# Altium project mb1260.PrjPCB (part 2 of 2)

## Sheet STM32F7.SchDoc: STM32F723e Connexion
size A3; Author: N.P; CompanyName: STMicroelectronics; Organization: MCD/APPLIS/LMS; DocumentNumber: MB1260; Revision: D-01; SheetNumber: 3; SheetTotal: 12; Project: STM32F723e-DISCO; BOM Version: D-01
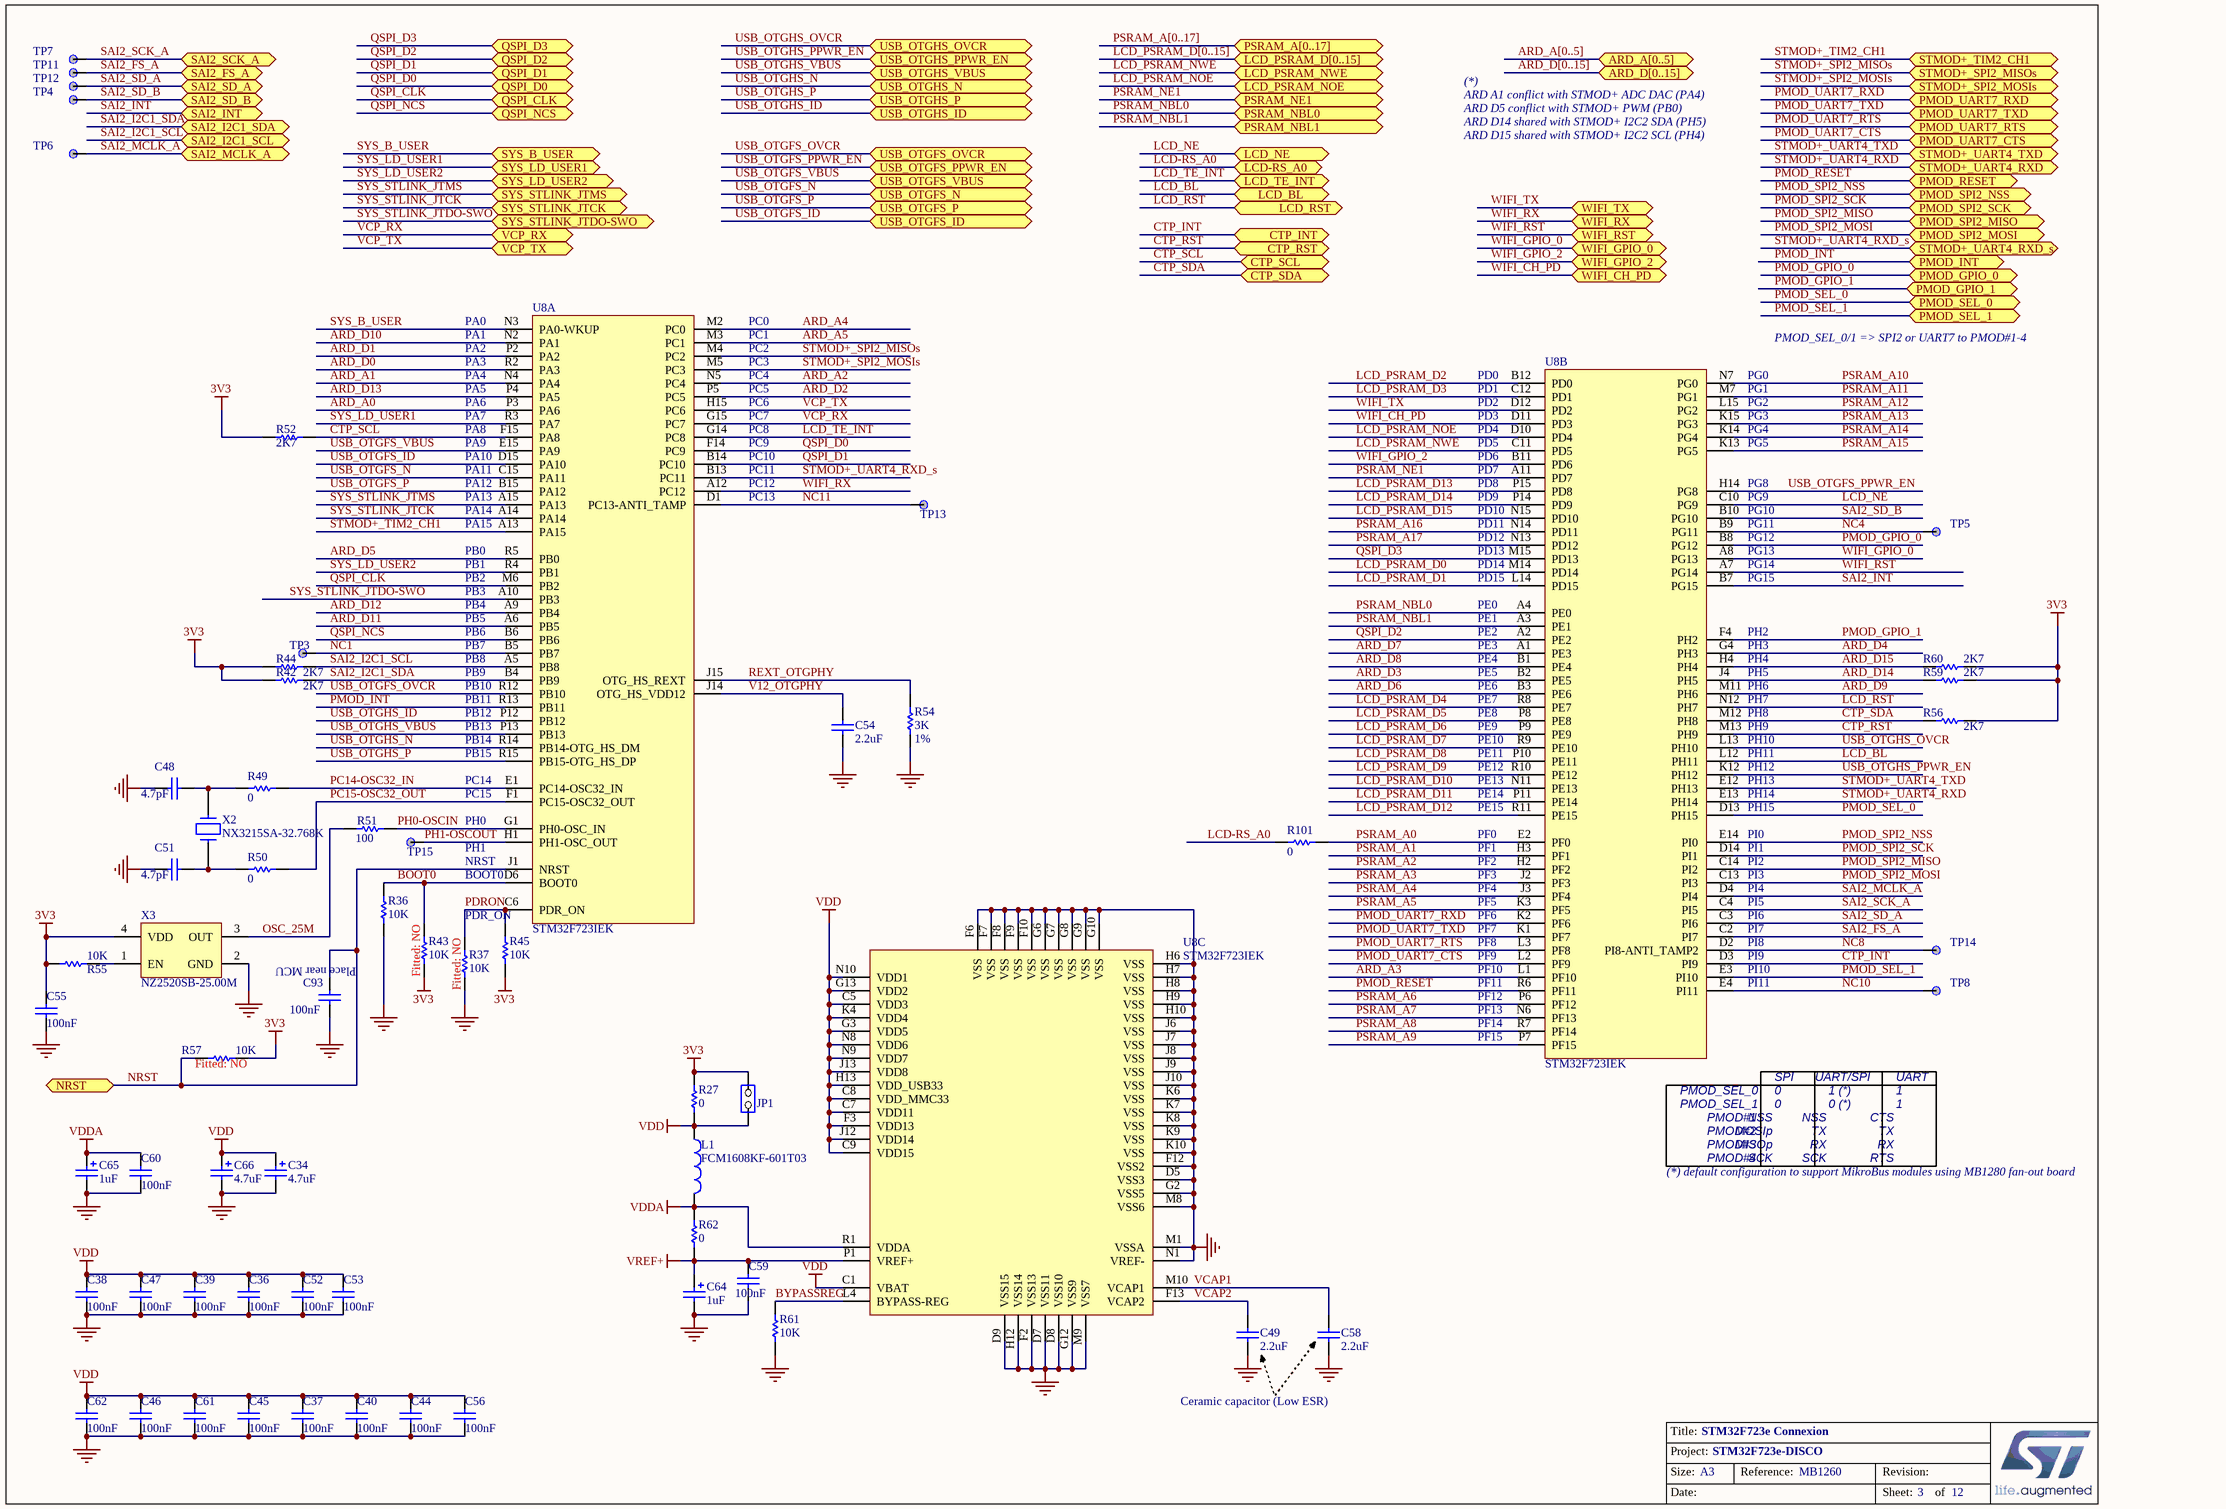
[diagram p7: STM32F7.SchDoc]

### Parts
C34  4.7uF  [TAN-A]
C36  100nF  [0402C]
C37  100nF  [0402C]
C38  100nF  [0402C]
C39  100nF  [0402C]
C40  100nF  [0402C]
C44  100nF  [0402C]
C45  100nF  [0402C]
C46  100nF  [0402C]
C47  100nF  [0402C]
C48  value 4.7pF  [0402C]  (hidden comment: 4.7pF_NPO_-+0.25pF_0402)
C49  2.2uF  [1206C]
C51  value 4.7pF  [0402C]  (hidden comment: 4.7pF_NPO_-+0.25pF_0402)
C52  100nF  [0402C]
C53  100nF  [0402C]
C54  value 2.2uF  [0603C]  (hidden comment: 2.2uF_X5R_10%_0603)
C55  100nF  [0402C]
C56  100nF  [0402C]
C58  2.2uF  [1206C]
C59  100nF  [0402C]
C60  100nF  [0402C]
C61  100nF  [0402C]
C62  100nF  [0402C]
C64  1uF  [TAN-A]
C65  1uF  [TAN-A]
C66  4.7uF  [TAN-A]
C93  100nF  [0402C]
JP1  JP2  [SIP2]  (value not drawn)
L1  FCM1608KF-601T03  [0603L]
R27  value 0  [0603R-GS]  (hidden comment: 0_5%_0603)
R36  10K  [0402R]
R37  Fitted: NO  [0402R]  (hidden comment: 10K)
R42  2K7  [0402R]
R43  Fitted: NO  [0402R]  (hidden comment: 10K)
R44  2K7  [0402R]
R45  10K  [0402R]
R49  0  [0402R]
R50  0  [0402R]
R51  100  [0402R]
R52  2K7  [0402R]
R54  3K  Tolerance: 1%  [0402R]
R55  10K  [0402R]
R56  2K7  [0402R]
R57  Fitted: NO  [0402R]  (hidden comment: 10K)
R59  2K7  [0402R]
R60  2K7  [0402R]
R61  10K  [0402R]
R62  value 0  [0603R-GS]  (hidden comment: 0_5%_0603)
R101  0  [0402R]
TP3  TP  [TP_C40]  (value not drawn)
TP4  TP  [TP_C40]  (value not drawn)
TP5  TP  [TP_C40]  (value not drawn)
TP6  TP  [TP_C40]  (value not drawn)
TP7  TP  [TP_C40]  (value not drawn)
TP8  TP  [TP_C40]  (value not drawn)
TP11  TP  [TP_C40]  (value not drawn)
TP12  TP  [TP_C40]  (value not drawn)
TP13  TP  [TP_C40]  (value not drawn)
TP14  TP  [TP_C40]  (value not drawn)
TP15  TP  [TP_C40]  (value not drawn)
U8  STM32F723IEK  [BGA176_0R65_10x10]  (parts A,B,C of 3)
X2  NX3215SA-32.768K  [XTAL_2SM_3R2X1R5]
X3  NZ2520SB-25.00M  [OSC_4SM_2R5X2]

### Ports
ARD_A[0..5], ARD_D[0..15], CTP_INT, CTP_RST, CTP_SCL, CTP_SDA, LCD-RS_A0, LCD_BL, LCD_NE, LCD_PSRAM_D[0..15], LCD_PSRAM_NOE, LCD_PSRAM_NWE, LCD_RST, LCD_TE_INT, NRST, PMOD_GPIO_0, PMOD_GPIO_1, PMOD_INT, PMOD_RESET, PMOD_SEL_0, PMOD_SEL_1, PMOD_SPI2_MISO, PMOD_SPI2_MOSI, PMOD_SPI2_NSS, PMOD_SPI2_SCK, PMOD_UART7_CTS, PMOD_UART7_RTS, PMOD_UART7_RXD, PMOD_UART7_TXD, PSRAM_A[0..17], PSRAM_NBL0, PSRAM_NBL1, PSRAM_NE1, QSPI_CLK, QSPI_D0, QSPI_D1, QSPI_D2, QSPI_D3, QSPI_NCS, SAI2_FS_A, SAI2_I2C1_SCL, SAI2_I2C1_SDA, SAI2_INT, SAI2_MCLK_A, SAI2_SCK_A, SAI2_SD_A, SAI2_SD_B, STMOD+_SPI2_MISOs, STMOD+_SPI2_MOSIs, STMOD+_TIM2_CH1, STMOD+_UART4_RXD, STMOD+_UART4_RXD_s, STMOD+_UART4_TXD, SYS_B_USER, SYS_LD_USER1, SYS_LD_USER2, SYS_STLINK_JTCK, SYS_STLINK_JTDO-SWO, SYS_STLINK_JTMS, USB_OTGFS_ID, USB_OTGFS_N, USB_OTGFS_OVCR, USB_OTGFS_P, USB_OTGFS_PPWR_EN, USB_OTGFS_VBUS, USB_OTGHS_ID, USB_OTGHS_N, USB_OTGHS_OVCR, USB_OTGHS_P, USB_OTGHS_PPWR_EN, USB_OTGHS_VBUS, VCP_RX, VCP_TX, WIFI_CH_PD, WIFI_GPIO_0, WIFI_GPIO_2, WIFI_RST, WIFI_RX, WIFI_TX

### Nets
3V3: C55.2 JP1.2(NO) R27.2 R42.1 R43.1 R44.1 R45.1 R52.1 R55.1 R56.2 R57.2 R59.2 R60.2 X3.4(VDD)
GND: C34.2 C36.1 C37.1 C38.1 C39.1 C40.1 C44.1 C45.1 C46.1 C47.1 C48.1 C49.1 C51.1 C52.1 C53.1 C54.1 C55.1 C56.1 C58.1 C59.1 C60.1 C61.1 C62.1 C64.2 C65.2 C66.2 C93.1 R36.1 R37.1 R54.1 R61.1 U8.D5(VSS3) U8.D7(VSS11) U8.D8(VSS10) U8.D9(VSS15) U8.F2(VSS13) U8.F6(VSS) U8.F7(VSS) U8.F8(VSS) U8.F9(VSS) U8.F10(VSS) U8.F12(VSS2) U8.G2(VSS5) U8.G6(VSS) U8.G7(VSS) U8.G8(VSS) U8.G9(VSS) U8.G10(VSS) U8.G12(VSS9) U8.H6(VSS) U8.H7(VSS) U8.H8(VSS) U8.H9(VSS) U8.H10(VSS) U8.H12(VSS14) U8.J6(VSS) U8.J7(VSS) U8.J8(VSS) U8.J9(VSS) U8.J10(VSS) U8.K6(VSS) U8.K7(VSS) U8.K8(VSS) U8.K9(VSS) U8.K10(VSS) U8.M1(VSSA) U8.M8(VSS6) U8.M9(VSS7) U8.N1(VREF-) X3.2(GND)
VDD: C34.1 C36.2 C37.2 C38.2 C39.2 C40.2 C44.2 C45.2 C46.2 C47.2 C52.2 C53.2 C56.2 C61.2 C62.2 C66.1 JP1.1(COMMON) L1.1 R27.1 U8.C1(VBAT) U8.C5(VDD3) U8.C7(VDD11) U8.C8(VDD_MMC33) U8.C9(VDD15) U8.F3(VDD13) U8.G3(VDD5) U8.G13(VDD2) U8.H13(VDD_USB33) U8.J12(VDD14) U8.J13(VDD8) U8.K4(VDD4) U8.N8(VDD6) U8.N9(VDD7) U8.N10(VDD1)
VDDA: C60.2 C65.1 L1.2 R62.2 U8.R1(VDDA)
VREF+: C59.2 C64.1 R62.1 U8.P1(VREF+)
ARD_A0: U8.P3(PA6)
ARD_A1: U8.N4(PA4)
ARD_A2: U8.N5(PC4)
ARD_A3: U8.L1(PF10)
ARD_A4: U8.M2(PC0)
ARD_A5: U8.M3(PC1)
ARD_D0: U8.R2(PA3)
ARD_D1: U8.P2(PA2)
ARD_D2: U8.P5(PC5)
ARD_D3: U8.B2(PE5)
ARD_D4: U8.G4(PH3)
ARD_D5: U8.R5(PB0)
ARD_D6: U8.B3(PE6)
ARD_D7: U8.A1(PE3)
ARD_D8: U8.B1(PE4)
ARD_D9: U8.M11(PH6)
ARD_D10: U8.N2(PA1)
ARD_D11: U8.A6(PB5)
ARD_D12: U8.A9(PB4)
ARD_D13: U8.P4(PA5)
ARD_D14: R59.1 U8.J4(PH5)
ARD_D15: R60.1 U8.H4(PH4)
BOOT0: R36.2 R43.2 U8.D6(BOOT0)
BYPASSREG: R61.2 U8.L4(BYPASS-REG)
CTP_INT: U8.D3(PI9) ; port CTP_INT
CTP_RST: U8.M13(PH9) ; port CTP_RST
CTP_SCL: R52.2 U8.F15(PA8) ; port CTP_SCL
CTP_SDA: R56.1 U8.M12(PH8) ; port CTP_SDA
LCD-RS_A0: R101.2 ; port LCD-RS_A0
LCD_BL: U8.L12(PH11) ; port LCD_BL
LCD_NE: U8.C10(PG9) ; port LCD_NE
LCD_PSRAM_D0: U8.M14(PD14)
LCD_PSRAM_D1: U8.L14(PD15)
LCD_PSRAM_D2: U8.B12(PD0)
LCD_PSRAM_D3: U8.C12(PD1)
LCD_PSRAM_D4: U8.R8(PE7)
LCD_PSRAM_D5: U8.P8(PE8)
LCD_PSRAM_D6: U8.P9(PE9)
LCD_PSRAM_D7: U8.R9(PE10)
LCD_PSRAM_D8: U8.P10(PE11)
LCD_PSRAM_D9: U8.R10(PE12)
LCD_PSRAM_D10: U8.N11(PE13)
LCD_PSRAM_D11: U8.P11(PE14)
LCD_PSRAM_D12: U8.R11(PE15)
LCD_PSRAM_D13: U8.P15(PD8)
LCD_PSRAM_D14: U8.P14(PD9)
LCD_PSRAM_D15: U8.N15(PD10)
LCD_PSRAM_NOE: U8.D10(PD4) ; port LCD_PSRAM_NOE
LCD_PSRAM_NWE: U8.C11(PD5) ; port LCD_PSRAM_NWE
LCD_RST: U8.N12(PH7) ; port LCD_RST
LCD_TE_INT: U8.G14(PC8) ; port LCD_TE_INT
NC1: TP3.1 U8.B5(PB7)
NC4: TP5.1 U8.B9(PG11)
NC8: TP14.1 U8.D2(PI8-ANTI_TAMP2)
NC10: TP8.1 U8.E4(PI11)
NC11: TP13.1 U8.D1(PC13-ANTI_TAMP)
NRST: C93.2 R57.1 U8.J1(NRST) ; port NRST
OSC_25M: R51.1 X3.3(OUT)
PC14-OSC32_IN: R49.2 U8.E1(PC14-OSC32_IN)
PC15-OSC32_OUT: R50.2 U8.F1(PC15-OSC32_OUT)
PDRON: R37.2 R45.2 U8.C6(PDR_ON)
PH0-OSCIN: R51.2 U8.G1(PH0-OSC_IN)
PH1-OSCOUT: TP15.1 U8.H1(PH1-OSC_OUT)
PMOD_GPIO_0: U8.B8(PG12) ; port PMOD_GPIO_0
PMOD_GPIO_1: U8.F4(PH2) ; port PMOD_GPIO_1
PMOD_INT: U8.R13(PB11) ; port PMOD_INT
PMOD_RESET: U8.R6(PF11) ; port PMOD_RESET
PMOD_SEL_0: U8.D13(PH15) ; port PMOD_SEL_0
PMOD_SEL_1: U8.E3(PI10) ; port PMOD_SEL_1
PMOD_SPI2_MISO: U8.C14(PI2) ; port PMOD_SPI2_MISO
PMOD_SPI2_MOSI: U8.C13(PI3) ; port PMOD_SPI2_MOSI
PMOD_SPI2_NSS: U8.E14(PI0) ; port PMOD_SPI2_NSS
PMOD_SPI2_SCK: U8.D14(PI1) ; port PMOD_SPI2_SCK
PMOD_UART7_CTS: U8.L2(PF9) ; port PMOD_UART7_CTS
PMOD_UART7_RTS: U8.L3(PF8) ; port PMOD_UART7_RTS
PMOD_UART7_RXD: U8.K2(PF6) ; port PMOD_UART7_RXD
PMOD_UART7_TXD: U8.K1(PF7) ; port PMOD_UART7_TXD
PSRAM_A0: R101.1 U8.E2(PF0)
PSRAM_A1: U8.H3(PF1)
PSRAM_A2: U8.H2(PF2)
PSRAM_A3: U8.J2(PF3)
PSRAM_A4: U8.J3(PF4)
PSRAM_A5: U8.K3(PF5)
PSRAM_A6: U8.P6(PF12)
PSRAM_A7: U8.N6(PF13)
PSRAM_A8: U8.R7(PF14)
PSRAM_A9: U8.P7(PF15)
PSRAM_A10: U8.N7(PG0)
PSRAM_A11: U8.M7(PG1)
PSRAM_A12: U8.L15(PG2)
PSRAM_A13: U8.K15(PG3)
PSRAM_A14: U8.K14(PG4)
PSRAM_A15: U8.K13(PG5)
PSRAM_A16: U8.N14(PD11)
PSRAM_A17: U8.N13(PD12)
PSRAM_NBL0: U8.A4(PE0) ; port PSRAM_NBL0
PSRAM_NBL1: U8.A3(PE1) ; port PSRAM_NBL1
PSRAM_NE1: U8.A11(PD7) ; port PSRAM_NE1
QSPI_CLK: U8.M6(PB2) ; port QSPI_CLK
QSPI_D0: U8.F14(PC9) ; port QSPI_D0
QSPI_D1: U8.B14(PC10) ; port QSPI_D1
QSPI_D2: U8.A2(PE2) ; port QSPI_D2
QSPI_D3: U8.M15(PD13) ; port QSPI_D3
QSPI_NCS: U8.B6(PB6) ; port QSPI_NCS
REXT_OTGPHY: R54.2 U8.J15(OTG_HS_REXT)
SAI2_FS_A: TP11.1 U8.C2(PI7) ; port SAI2_FS_A
SAI2_I2C1_SCL: R44.2 U8.A5(PB8) ; port SAI2_I2C1_SCL
SAI2_I2C1_SDA: R42.2 U8.B4(PB9) ; port SAI2_I2C1_SDA
SAI2_INT: U8.B7(PG15) ; port SAI2_INT
SAI2_MCLK_A: TP6.1 U8.D4(PI4) ; port SAI2_MCLK_A
SAI2_SCK_A: TP7.1 U8.C4(PI5) ; port SAI2_SCK_A
SAI2_SD_A: TP12.1 U8.C3(PI6) ; port SAI2_SD_A
SAI2_SD_B: TP4.1 U8.B10(PG10) ; port SAI2_SD_B
STMOD+_SPI2_MISOs: U8.M4(PC2) ; port STMOD+_SPI2_MISOs
STMOD+_SPI2_MOSIs: U8.M5(PC3) ; port STMOD+_SPI2_MOSIs
STMOD+_TIM2_CH1: U8.A13(PA15) ; port STMOD+_TIM2_CH1
STMOD+_UART4_RXD: U8.E13(PH14) ; port STMOD+_UART4_RXD
STMOD+_UART4_RXD_s: U8.B13(PC11) ; port STMOD+_UART4_RXD_s
STMOD+_UART4_TXD: U8.E12(PH13) ; port STMOD+_UART4_TXD
SYS_B_USER: U8.N3(PA0-WKUP) ; port SYS_B_USER
SYS_LD_USER1: U8.R3(PA7) ; port SYS_LD_USER1
SYS_LD_USER2: U8.R4(PB1) ; port SYS_LD_USER2
SYS_STLINK_JTCK: U8.A14(PA14) ; port SYS_STLINK_JTCK
SYS_STLINK_JTDO-SWO: U8.A10(PB3) ; port SYS_STLINK_JTDO-SWO
SYS_STLINK_JTMS: U8.A15(PA13) ; port SYS_STLINK_JTMS
USB_OTGFS_ID: U8.D15(PA10) ; port USB_OTGFS_ID
USB_OTGFS_N: U8.C15(PA11) ; port USB_OTGFS_N
USB_OTGFS_OVCR: U8.R12(PB10) ; port USB_OTGFS_OVCR
USB_OTGFS_P: U8.B15(PA12) ; port USB_OTGFS_P
USB_OTGFS_PPWR_EN: U8.H14(PG8) ; port USB_OTGFS_PPWR_EN
USB_OTGFS_VBUS: U8.E15(PA9) ; port USB_OTGFS_VBUS
USB_OTGHS_ID: U8.P12(PB12) ; port USB_OTGHS_ID
USB_OTGHS_N: U8.R14(PB14-OTG_HS_DM) ; port USB_OTGHS_N
USB_OTGHS_OVCR: U8.L13(PH10) ; port USB_OTGHS_OVCR
USB_OTGHS_P: U8.R15(PB15-OTG_HS_DP) ; port USB_OTGHS_P
USB_OTGHS_PPWR_EN: U8.K12(PH12) ; port USB_OTGHS_PPWR_EN
USB_OTGHS_VBUS: U8.P13(PB13) ; port USB_OTGHS_VBUS
V12_OTGPHY: C54.2 U8.J14(OTG_HS_VDD12)
VCAP1: C58.2 U8.M10(VCAP1)
VCAP2: C49.2 U8.F13(VCAP2)
VCP_RX: U8.G15(PC7) ; port VCP_RX
VCP_TX: U8.H15(PC6) ; port VCP_TX
WIFI_CH_PD: U8.D11(PD3) ; port WIFI_CH_PD
WIFI_GPIO_0: U8.A8(PG13) ; port WIFI_GPIO_0
WIFI_GPIO_2: U8.B11(PD6) ; port WIFI_GPIO_2
WIFI_RST: U8.A7(PG14) ; port WIFI_RST
WIFI_RX: U8.A12(PC12) ; port WIFI_RX
WIFI_TX: U8.D12(PD2) ; port WIFI_TX
NetC48_2: C48.2 R49.1 X2.1
NetC51_2: C51.2 R50.1 X2.2
NetR55_2: R55.2 X3.1(EN)

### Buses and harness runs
bus ARD_A[0..5] = port ARD_A[0..5]
bus ARD_D[0..15] = port ARD_D[0..15]
bus LCD_PSRAM_D[0..15] = port LCD_PSRAM_D[0..15]
bus PSRAM_A[0..17] = port PSRAM_A[0..17]

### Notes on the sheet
- (*)
  ARD A1 conflict with STMOD+ ADC DAC (PA4)
  ARD D5 conflict with STMOD+ PWM (PB0)
  ARD D14 shared with STMOD+ I2C2 SDA (PH5)
  ARD D15 shared with STMOD+ I2C2 SCL (PH4)
- (near U8) PA0
- (near U8) PA1
- (near U8) PA2
- (near U8) PA3
- (near U8) PA4
- PC0
- PC1
- PC2
- PC3
- PC4
- (near U8) PD0
- (near U8) PG0
- PMOD_SEL_0/1 => SPI2 or UART7 to PMOD#1-4
- (near U8) PA5
- (near U8) PA6
- (near U8) PA7
- (near U8) PA8
- (near U8) PA9
- PC5
- PC6
- PC7
- PC8
- PC9
- (near U8) PD1
- (near U8) PD2
- (near U8) PD3
- (near U8) PD4
- (near U8) PD5
- (near U8) PG1
- (near U8) PG2
- (near U8) PG3
- (near U8) PG4
- (near U8) PG5
- (near U8) PA10
- (near U8) PA11
- (near U8) PA12
- (near U8) PA13
- (near U8) PA14
- PC10
- PC11
- PC12
- PC13
- (near U8) PD6
- (near U8) PD7
- (near U8) PD8
- (near U8) PD9
- (near U8) PD10
- (near U8) PG8
- (near U8) PG9
- (near U8) PG10
- (near U8) PA15
- (near U8) PB0
- (near U8) PB1
- (near U8) PB2
- (near U8) PD11
- (near U8) PD12
- (near U8) PD13
- (near U8) PD14
- (near U8) PD15
- (near U8) PG11
- (near U8) PG12
- (near U8) PG13
- (near U8) PG14
- (near U8) PG15
- (near U8) PB3
- (near U8) PB4
- (near U8) PB5
- (near U8) PB6
- (near U8) PB7
- (near U8) PE0
- (near U8) PE1
- (near U8) PE2
- (near U8) PE3
- (near U8) PH2
- (near U8) PH3
- (near U8) PB8
- (near U8) PB9
- (near U8) PB10
- (near U8) PB11
- (near U8) PB12
- (near U8) PE4
- (near U8) PE5
- (near U8) PE6
- (near U8) PE7
- (near U8) PE8
- (near U8) PH4
- (near U8) PH5
- (near U8) PH6
- (near U8) PH7
- (near U8) PH8
- (near U8) PB13
- (near U8) PB14
- (near U8) PB15
- (near U8) PC14
- (near U8) PE9
- (near U8) PE10
- (near U8) PE11
- (near U8) PE12
- (near U8) PE13
- (near U8) PH9
- (near U8) PH10
- (near U8) PH11
- (near U8) PH12
- (near U8) PH13
- PC15
- PH0
- PH1
- (near U8) PE14
- (near U8) PE15
- (near U8) PF0
- (near U8) PF1
- (near U8) PH14
- (near U8) PH15
- (near U8) PI0
- (near U8) PI1
- NRST
- BOOT0
- (near R45) PDR_ON
- (near U8) PF2
- (near U8) PF3
- (near U8) PF4
- (near U8) PF5
- (near U8) PF6
- (near U8) PI2
- (near U8) PI3
- (near U8) PI4
- (near U8) PI5
- (near U8) PI6
- (near C93) Place near MCU
- (near U8) PF7
- (near U8) PF8
- (near U8) PF9
- (near U8) PF10
- (near U8) PF11
- (near U8) PI7
- (near U8) PI8
- (near U8) PI9
- (near U8) PI10
- (near U8) PI11
- (near U8) PF12
- (near U8) PF13
- (near U8) PF14
- (near U8) PF15
- (near U8) PMOD_SEL_0
- PMOD_SEL_1
- PMOD#1
- 0
- NSS
- SPI
- UART/SPI
- 0 (*)
- 1 (*)
- CTS
- UART
- 1
- (*) default configuration to support MikroBus modules using MB1280 fan-out board
- PMOD#2
- PMOD#3
- PMOD#4
- MOSIp
- MISOp
- SCK
- TX
- RX
- RTS
- Ceramic capacitor (Low ESR)

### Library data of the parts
C34 C66 = Cap_4.7uF_POL_10%_TANA: Polarized Capacitor,4.7uF,16V,10%,typeA,AVX; Manuf_Part_1: TAJA475K016R; Ordered by: Subcon; Fitted: YES
C36-C40 C44-C47 C52 C53 C55 C56 C59-C62 C93 = Cap_100nF_X7R_10%_0402: Capacitor,100nF,16V,X7R,10%,0402,YAGEO; Manuf_Part_1: CC0402KRX7R7BB104; Ordered by: Subcon; Fitted: YES
C48 C51 = Cap_4.7pF_NPO_-+0.25pF_0402: Capacitor, 4.7pF, 50V, NPO, -+0.25pF, 0402, YAGEO; Manuf_Part_1: CC0402CRNPO9BN4R7; Order: 311-1633-2-ND; Ordered by: Subcon; Fitted: YES
C49 C58 = Cap_2.2uF_X7R_10%_1206: Capacitor,2.2uF,16V, X7R,10%,1206,YAGEO; Manuf_Part_1: CC1206KKX7R7BB225; Manuf_Part_2: C1206C225K4RAC; Manuf_2: KEMET; Ordered by: Subcon; Fitted: YES
C54 = Cap_2.2uF_X5R_10%_0603: Capacitor,2.2uF,10V, X5R,10%,0603,YAGEO; Manuf_Part_1: CC0603KRX5R6BB225; Manuf_Part_2: C0603C225K8PACTU; Manuf_2: KEMET; Ordered by: Subcon; Fitted: YES
C64 C65 = Cap_1uF_POL_10%_TANA: Polarized Capacitor,1uF,16V,10%,typeA,AVX; Manuf_Part_1: TAJA105K016R; Ordered by: Subcon; Fitted: YES
JP1 = JP2: Fitted: NO; Ordered by: Subcon
L1 = BEAD_600R_350MA_0603: Bead,600R,350mA,0603,FCM1608KF-601T03,Tai-tech; Manuf_2: TDK; Manuf_Part_2: MPZ1608S300A; Manuf_Part_3: BLM18PG121SN1D; Manuf_3: MURATA; Value: 100uH; Description_2: Bead,30R,5A,0603,MPZ1608S300A,TDK; Description_3: Bead,120R,2A,0603,BLM18PG121SN1D,MURATA; Ordered by: Subcon; Fitted: YES
R27 R62 = Res_0_5%_0603: Resistor,0,0603,5%,YAGEO; Manuf_Part_1: RC0603JR-070RL; Order: 2363481; Ordered by: Subcon; Fitted: YES
R36 R45 R55 R61 = Res_10K_1%_0402: Resistor,10K,0402,1%,YAGEO; Manuf_Part_1: RC0402FR-0710KL; Ordered by: Subcon; Fitted: YES
R37 R43 R57 = Res_10K_1%_0402: Resistor,10K,0402,1%,YAGEO; Manuf_Part_1: RC0402FR-0710KL; Ordered by: Subcon
R42 R44 R52 R56 R59 R60 = Res_2K7_1%_0402: Resistor,2K7,0402,1%,YAGEO; Manuf_Part_1: RC0402FR-072K7L; Ordered by: Subcon; Fitted: YES
R49 R50 R101 = Res_0_5%_0402: Resistor,0,0402,5%,YAGEO; Manuf_Part_1: RC0402JR-070RL; Order: 2363467; Ordered by: Subcon; Fitted: YES
R51 = Res_100_1%_0402: Resistor,100,0402,1%,YAGEO; Manuf_Part_1: RC0402FR-07100RL; Order: 9239111; Ordered by: Subcon; Fitted: YES
R54 = Res_3K_1%_0402: Resistor 3K 0402 1% YAGEO; Manuf_Part_1: RC0402FR-073KL; Ordered by: Subcon; Fitted: YES
TP3-TP8 TP11-TP15 = TP: Test Point; Fitted: NO; Ordered by: Subcon
U8 = STM32F723IEK: STM32F723IEK  (STM32F7 LittleBirdie) BGA176; Manuf_1: STM; Fitted: YES; Ordered by: ST
X2 = XTAL_32K_NX3215SA: Crystal 32.768kHz, 6pF, -+20PPM, R=50K, SMD; Manuf_1: NDK; Manuf_Part_1: NX3215SA 32.768KHz EXS00A-MU00525; ECCN_US/EU: EAR99/NEC; Ref St: 9157034; NDK Ref: X3101802; Provided: ST; Fitted: YES
X3 = OSC_25M_NZ2520SB: Oscillator 25.00Mhz, -+50PPM, 3.3V, Temp -55 to +125°C; Manuf_Part_1: NZ2520SB 25MHz END4869B; Manuf_1: NDK; Manuf_Part_2: KC2520B25.0000C10E00; Manuf_2: AVX Corp/Kyocera Corp; ECCN_US/EU: EAR99/NEC; Ref St: 9157031; Provided: ST; Fitted: YES

## Sheet LCD_FRIDA.SchDoc: LCD_Frida
size A3; Author: N.P; CompanyName: STMicroelectronics; Organization: MCD/APPLICATIONS/LMS; DocumentNumber: MB1260; Revision: D-01; SheetNumber: 10; SheetTotal: 12; Project: STM32F723e-DISCO; PageSetup: Record=PageOptions¦CenterHorizontal=True¦CenterVertical=True¦PrintScale=1.00¦XCorrection=1.00¦YCorrection=1.00¦PrintKind=1¦BorderSize=5000000¦LeftOffset=0¦BottomOffset=0¦Orientation=2¦PaperLength=1000¦PaperWidth=1000¦Scale=100¦PaperSource=7¦PrintQuality=-3¦MediaType=1¦DitherType=10¦PrintScaleMode=1¦PaperKind=Letter¦PaperIndex=1; BOM Version: D-01
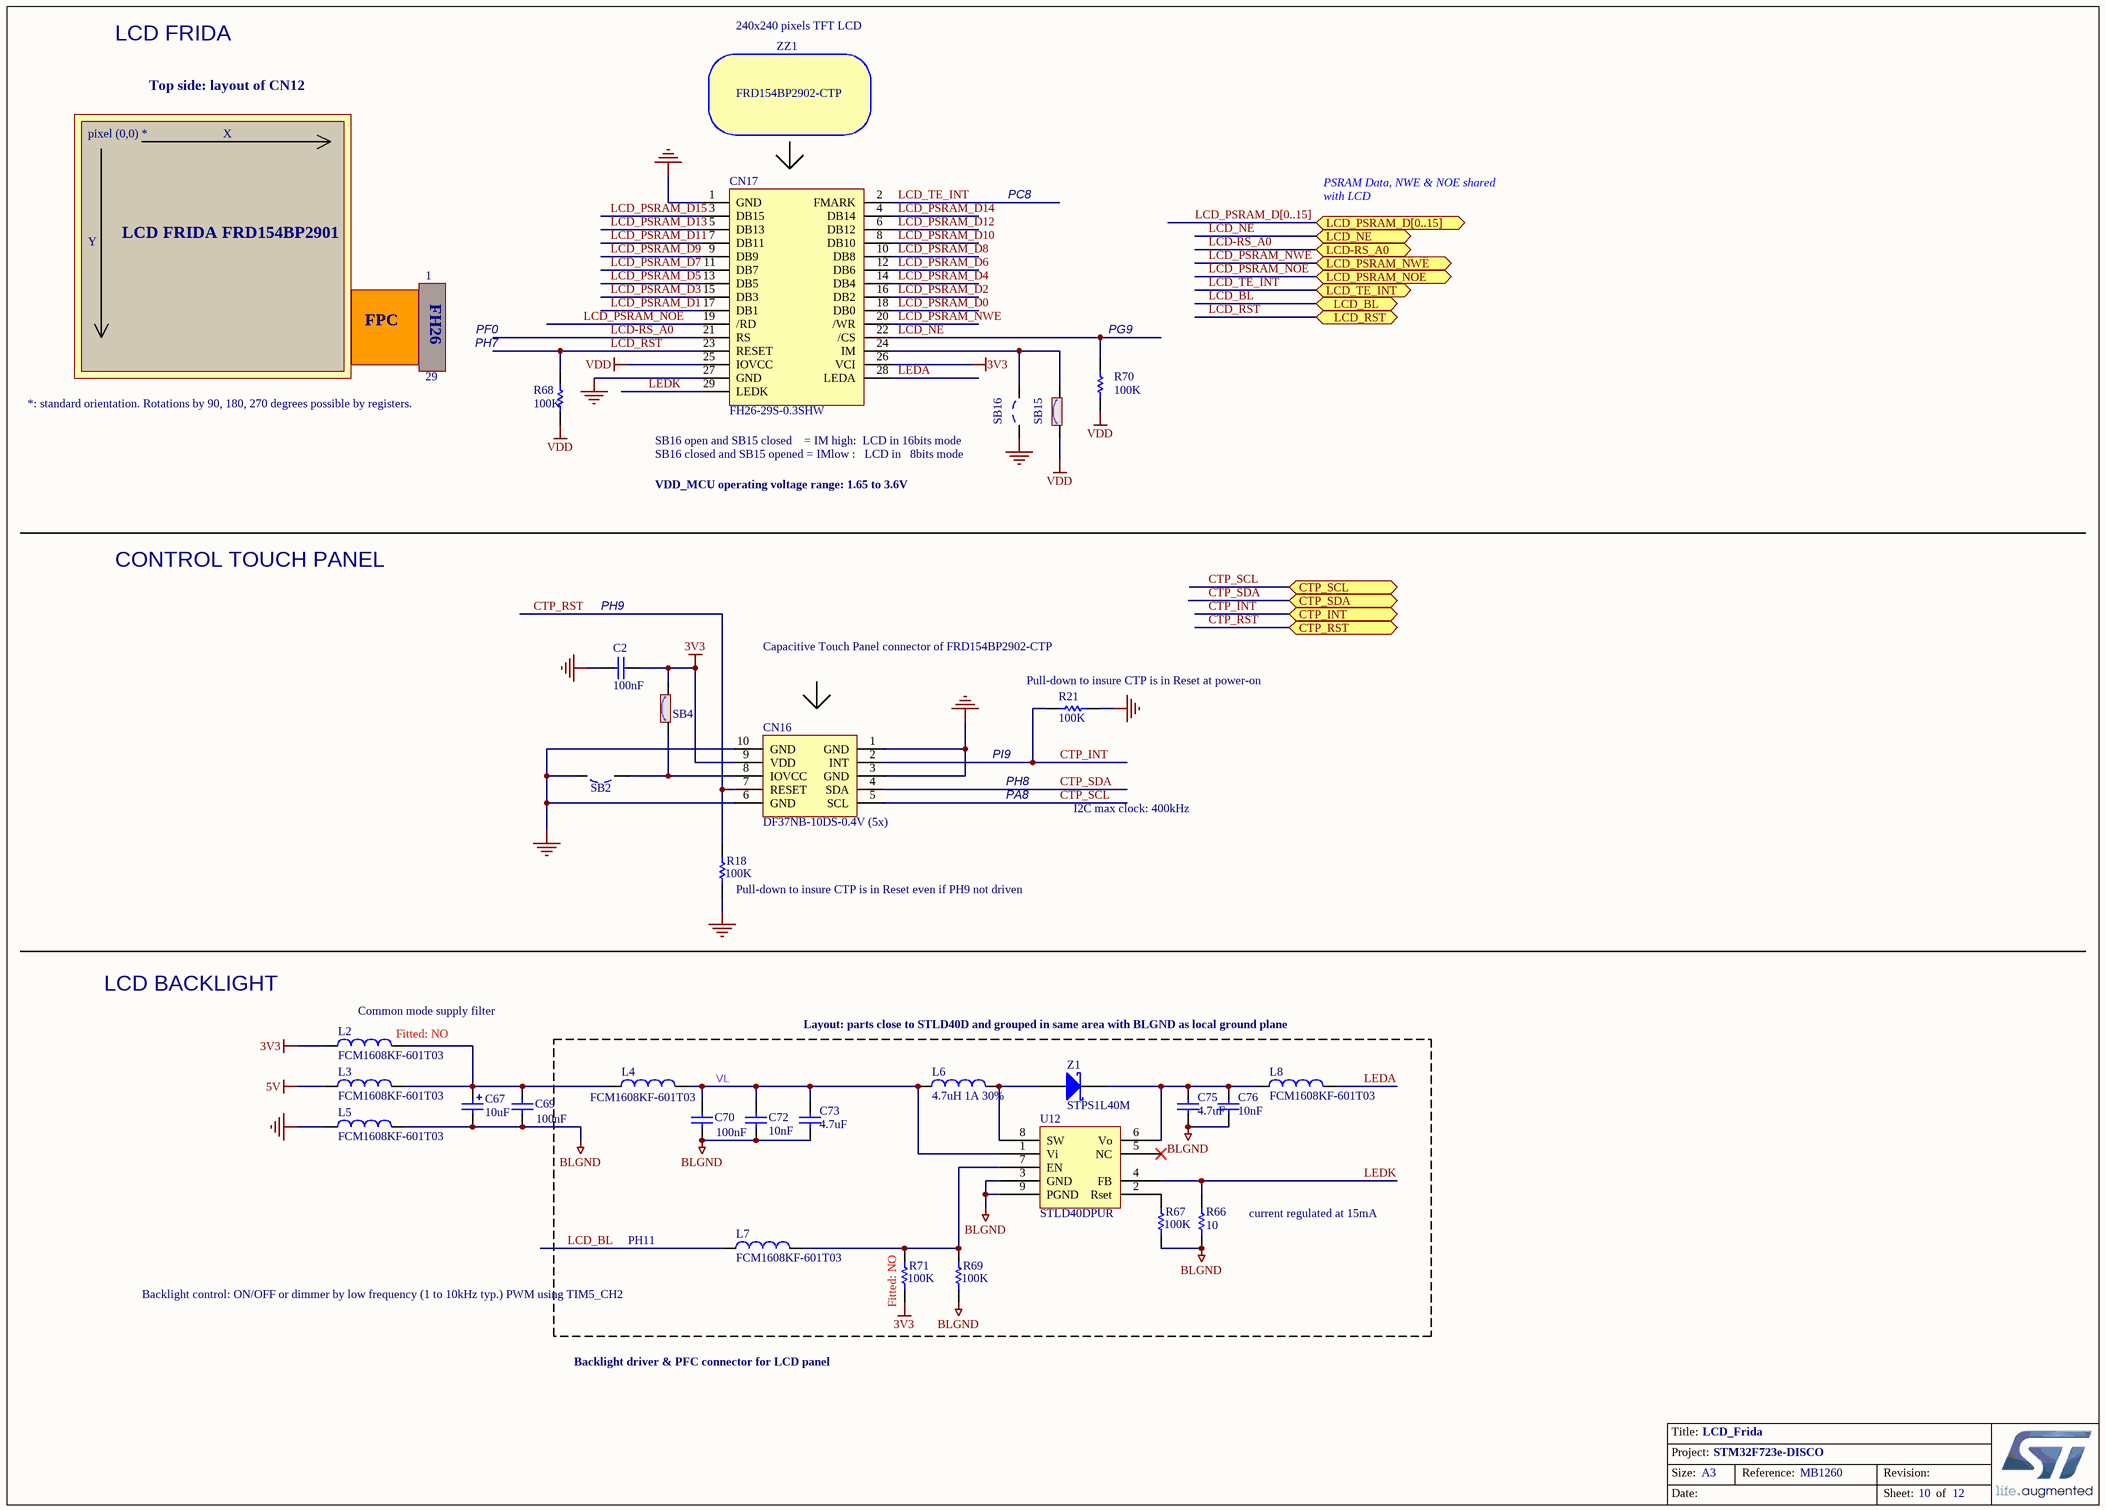
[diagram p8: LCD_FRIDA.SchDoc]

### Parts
C2  100nF  [0402C]
C67  value 10uF  [TAN-A]  (hidden comment: 10uF_POL_10%_TANA)
C69  100nF  [0402C]
C70  100nF  [0402C]
C72  value 10nF  [0603C]  (hidden comment: 10nF_X7R_10%_0603)
C73  value 4.7uF  [1206C]  (hidden comment: 4.7uF_X7R_10%_1206)
C75  value 4.7uF  [1206C]  (hidden comment: 4.7uF_X7R_10%_1206)
C76  value 10nF  [0603C]  (hidden comment: 10nF_X7R_10%_0603)
CN16  DF37NB-10DS-0.4V (5x)  [DF37NB-10DS-0R4V]
CN17  FH26-29S-0.3SHW  [FH26-29S-0R3SHW]
L2  FCM1608KF-601T03  Fitted: NO  [0603L]
L3  FCM1608KF-601T03  [0603L]
L4  FCM1608KF-601T03  [0603L]
L5  FCM1608KF-601T03  [0603L]
L6  4.7uH 1A 30%  [1210L]
L7  FCM1608KF-601T03  [0603L]
L8  FCM1608KF-601T03  [0603L]
R18  value 100K  [0402R]  (hidden comment: 100K_1%_0402)
R21  value 100K  [0402R]  (hidden comment: 100K_1%_0402)
R66  value 10  [0603R]  (hidden comment: 10_1%_0603)
R67  value 100K  [0402R]  (hidden comment: 100K_1%_0402)
R68  value 100K  [0402R]  (hidden comment: 100K_1%_0402)
R69  value 100K  [0402R]  (hidden comment: 100K_1%_0402)
R70  value 100K  [0402R]  (hidden comment: 100K_1%_0402)
R71  value 100K  Fitted: NO  [0402R]  (hidden comment: 100K_1%_0402)
SB2  Solder Bridge OFF  [JP2_SMD]  (value not drawn)
SB4  Solder Bridge ON  [JP2_SMD]  (value not drawn)
SB15  Solder Bridge ON  [JP2_SMD]  (value not drawn)
SB16  Solder Bridge OFF  [JP2_SMD]  (value not drawn)
U12  STLD40DPUR  [SON8_0R65_3X3]
Z1  STPS1L40M  [DO-216AA]
ZZ1  FRD154BP2902-CTP

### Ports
CTP_INT, CTP_RST, CTP_SCL, CTP_SDA, LCD-RS_A0, LCD_BL, LCD_NE, LCD_PSRAM_D[0..15], LCD_PSRAM_NOE, LCD_PSRAM_NWE, LCD_RST, LCD_TE_INT

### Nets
3V3: C2.1 CN16.9(VDD) CN17.26(VCI) L2.1 R71.1 SB4.2
5V: L3.1
BLGND: C67.2 C69.1 C70.1 C72.1 C73.1 C75.1 C76.1 L5.2 R66.1 R67.1 R69.1 U12.3(GND) U12.9(PGND)
GND: C2.2 CN16.1(GND) CN16.3(GND) CN16.6(GND) CN16.10(GND) CN17.1(GND) CN17.27(GND) L5.1 R18.1 R21.1 SB2.2 SB16.1
VDD: CN17.25(IOVCC) R68.1 R70.1 SB15.1
CTP_INT: CN16.2(INT) R21.2 ; port CTP_INT
CTP_RST: CN16.7(RESET) R18.2 ; port CTP_RST
CTP_SCL: CN16.5(SCL) ; port CTP_SCL
CTP_SDA: CN16.4(SDA) ; port CTP_SDA
LCD-RS_A0: CN17.21(RS) ; port LCD-RS_A0
LCD_BL: L7.1 ; port LCD_BL
LCD_NE: CN17.22(/CS) R70.2 ; port LCD_NE
LCD_PSRAM_D0: CN17.18(DB0)
LCD_PSRAM_D1: CN17.17(DB1)
LCD_PSRAM_D2: CN17.16(DB2)
LCD_PSRAM_D3: CN17.15(DB3)
LCD_PSRAM_D4: CN17.14(DB4)
LCD_PSRAM_D5: CN17.13(DB5)
LCD_PSRAM_D6: CN17.12(DB6)
LCD_PSRAM_D7: CN17.11(DB7)
LCD_PSRAM_D8: CN17.10(DB8)
LCD_PSRAM_D9: CN17.9(DB9)
LCD_PSRAM_D10: CN17.8(DB10)
LCD_PSRAM_D11: CN17.7(DB11)
LCD_PSRAM_D12: CN17.6(DB12)
LCD_PSRAM_D13: CN17.5(DB13)
LCD_PSRAM_D14: CN17.4(DB14)
LCD_PSRAM_D15: CN17.3(DB15)
LCD_PSRAM_NOE: CN17.19(/RD) ; port LCD_PSRAM_NOE
LCD_PSRAM_NWE: CN17.20(/WR) ; port LCD_PSRAM_NWE
LCD_RST: CN17.23(RESET) R68.2 ; port LCD_RST
LCD_TE_INT: CN17.2(FMARK) ; port LCD_TE_INT
LEDA: CN17.28(LEDA) L8.2
LEDK: CN17.29(LEDK) R66.2 U12.4(FB)
VL: C70.2 C72.2 C73.2 L4.2 L6.1 U12.1(Vi)
NetC67_1: C67.1 C69.2 L2.2 L3.2 L4.1
NetC75_2: C75.2 C76.2 L8.1 U12.6(Vo) Z1.2(K)
NetCN16_8: CN16.8(IOVCC) SB2.1 SB4.1
NetCN17_24: CN17.24(IM) SB15.2 SB16.2
NetL6_2: L6.2 U12.8(SW) Z1.1(A)
NetL7_2: L7.2 R69.2 R71.2 U12.7(EN)
NetR67_2: R67.2 U12.2(Rset)

Not connected (* = marked no-connect by the designer): U12 5(NC)*

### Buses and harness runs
bus LCD_PSRAM_D[0..15] = port LCD_PSRAM_D[0..15]

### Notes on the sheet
- LCD FRIDA
- 240x240 pixels TFT LCD
- Top side: layout of CN12
- pixel (0,0) *
- X
- Y
- LCD FRIDA FRD154BP2901
- PC8
- PSRAM Data, NWE & NOE shared with LCD
- 1
- FH26
- FPC
- 29
- PF0
- PH7
- (near R70) PG9
- (near R68) *: standard orientation. Rotations by 90, 180, 270 degrees possible by registers.
- SB16 open and SB15 closed    = IM high:  LCD in 16bits mode
  SB16 closed and SB15 opened = IMlow :   LCD in   8bits mode
- VDD_MCU operating voltage range: 1.65 to 3.6V
- CONTROL TOUCH PANEL
- PH9
- Capacitive Touch Panel connector of FRD154BP2902-CTP
- (near R21) Pull-down to insure CTP is in Reset at power-on
- PI9
- PH8
- PA8
- I2C max clock: 400kHz
- (near R18) Pull-down to insure CTP is in Reset even if PH9 not driven
- LCD BACKLIGHT
- (near L2) Common mode supply filter
- Layout: parts close to STLD40D and grouped in same area with BLGND as local ground plane
- PH11
- (near R66) current regulated at 15mA
- Backlight control: ON/OFF or dimmer by low frequency (1 to 10kHz typ.) PWM using TIM5_CH2
- Backlight driver & PFC connector for LCD panel

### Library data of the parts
C2 C69 C70 = Cap_100nF_X7R_10%_0402: as C36-C40 on sheet STM32F7
C67 = Cap_10uF_POL_10%_TANA: Polarized Capacitor,10uF,10V,10%,typeA,VISHAY; Manuf_Part_1: 293D106X9010A2TE3; Ordered by: Subcon; Fitted: YES
C72 C76 = Cap_10nF_X7R_10%_0603: Capacitor,10nF,50V,X7R,10%,0603,YAGEO; Manuf_Part_1: CC0603KRX7R9BB103; Ordered by: Subcon; Fitted: YES
C73 C75 = Cap_4.7uF_X7R_10%_1206: Capacitor,4.7uF,50V, X7R,10%,1206,AVX; Manuf_Part_1: 12065C475KAT2A; Ordered by: Subcon; Fitted: YES
CN16 = Header 5X2A: Header, 5-Pin, Dual row; Manuf_1: Hirose; Ordered by: Subcon; Fitted: YES
CN17 = FH26-29S-0.3SHW: 29pins FPC connector; Manuf_1: Hirose; Ordered by: Subcon; Fitted: YES
L2 = BEAD_600R_350MA_0603: Bead,600R,350mA,0603,FCM1608KF-601T03,Tai-tech; Manuf_2: TDK; Manuf_Part_2: MPZ1608S300A; Manuf_Part_3: BLM18PG121SN1D; Manuf_3: MURATA; Value: 100uH; Description_2: Bead,30R,5A,0603,MPZ1608S300A,TDK; Description_3: Bead,120R,2A,0603,BLM18PG121SN1D,MURATA; Fitted: NO; Ordered by: Subcon
L3-L5 L7 L8 = BEAD_600R_350MA_0603: as L1 on sheet STM32F7
L6 = Ind_4.7uH_1A_30%: FIXED IND 4.7UH 1A 180 MOHM 30% SMD; Manuf_Part_1: LQH32PN4R7NN0L; Manuf_1: MURATA; Order: 490-5338-1-ND; Ordered by: Subcon; Fitted: YES
R18 R21 R67-R70 = Res_100K_1%_0402: Resistor,100K,0402,1%,YAGEO; Manuf_Part_2: RT0402FRE07100KL; Manuf_Part_1: RC0402FR-07100KL; Ordered by: Subcon; Fitted: YES
R66 = Res_10_1%_0603: Resistor,10,0603,1%,ROHM,1/4W; Manuf_Part_1: ESR03EZPF10R0; Ordered by: Subcon; Fitted: YES
R71 = Res_100K_1%_0402: Resistor,100K,0402,1%,YAGEO; Manuf_Part_2: RT0402FRE07100KL; Manuf_Part_1: RC0402FR-07100KL; Ordered by: Subcon
SB2 SB16 = SB_OFF: Fitted: NO; Ordered by: Subcon
SB4 SB15 = SB_ON: Fitted: YES; Ordered by: Subcon
U12 = STLD40DPMR: White LED power supply for large display backlight; Manuf_1: STM; Ordered by: ST; Ref St: 9176009; ECCN_US/EU: EAR99/NEC; Fitted: YES
Z1 = D Schottky: Schottky Diode; Manuf_1: STM; Code - JEDEC: DO-214-AA; Ordered by: ST; Ref St: 9151085; ECCN_US/EU: EAR99/NEC; Fitted: YES
ZZ1 = BoM_Item: Frida LCD + Capacitive Touch Panel; Ordered by: Subcon; ECCN_US/EU: EAR99/NEC; Fitted: YES

## Sheet USB_OTG_HS.SchDoc: USB OTG HS PHY with micro A-B connector
size A4; Author: N.P; CompanyName: STMicroelectronics; Organization: MCD/APPLIS/LMS; DocumentNumber: MB1260; Revision: D-01; SheetNumber: 8; SheetTotal: 12; Project: STM32F723e-DISCO; BOM Version: D-01
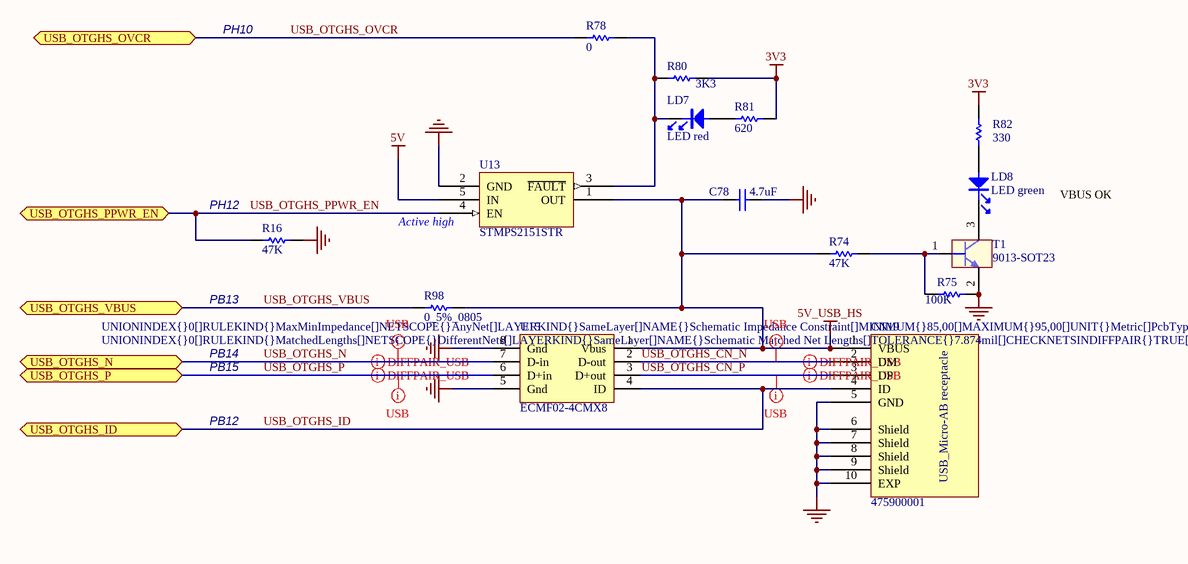
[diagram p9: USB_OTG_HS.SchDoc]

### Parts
C78  4.7uF  [0603C]
CN19  475900001  [MOLEX_47590001]
LD7  LED red  [0603D]
LD8  LED green  [0603D]
R16  value 47K  [0402R]  (hidden comment: 47K_1%_0402)
R74  value 47K  [0402R]  (hidden comment: 47K_1%_0402)
R75  value 100K  [0402R]  (hidden comment: 100K_1%_0402)
R78  0  [0402R]
R80  3K3  [0402R]
R81  value 620  [0603R]  (hidden comment: 620_1%_0603)
R82  value 330  [0603R]  (hidden comment: 330_1%_0603)
R98  0_5%_0805  [0805R]
T1  9013-SOT23  [SOT-23]
U13  STMPS2151STR  [SOT23-5]
U15  ECMF02-4CMX8  [QFN8_0R5_2R5X1R2]

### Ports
USB_OTGHS_ID, USB_OTGHS_N, USB_OTGHS_OVCR, USB_OTGHS_P, USB_OTGHS_PPWR_EN, USB_OTGHS_VBUS

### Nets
3V3: R80.1 R81.1 R82.2
5V: U13.5(IN)
5V_USB_HS: C78.1 CN19.1(VBUS) R74.2 R98.2 U13.1(OUT) U15.1(Vbus)
GND: C78.2 CN19.5(GND) CN19.6(Shield) CN19.7(Shield) CN19.8(Shield) CN19.9(Shield) CN19.10(EXP) R16.1 R75.2 T1.2(E) U13.2(GND) U15.5(Gnd) U15.8(Gnd)
USB_OTGHS_CN_N: CN19.2(DM) U15.2(D-out)
USB_OTGHS_CN_P: CN19.3(DP) U15.3(D+out)
USB_OTGHS_ID: CN19.4(ID) U15.4(ID) ; port USB_OTGHS_ID
USB_OTGHS_N: U15.7(D-in) ; port USB_OTGHS_N
USB_OTGHS_OVCR: R78.2 ; port USB_OTGHS_OVCR
USB_OTGHS_P: U15.6(D+in) ; port USB_OTGHS_P
USB_OTGHS_PPWR_EN: R16.2 U13.4(EN) ; port USB_OTGHS_PPWR_EN
USB_OTGHS_VBUS: R98.1 ; port USB_OTGHS_VBUS
NetLD7_1: LD7.1 R81.2
NetLD7_2: LD7.2 R78.1 R80.2 U13.3(~{FAULT})
NetLD8_1: LD8.1 R82.1
NetLD8_2: LD8.2 T1.3(C)
NetR74_1: R74.1 R75.1 T1.1(B)

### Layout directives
differential pair; rule Impedance Constraint [Min = 85.00    Max = 95.00    ]: USB_OTGHS_CN_N, USB_OTGHS_CN_P, USB_OTGHS_N, USB_OTGHS_P
rule Undefined; rule Matched Net Lengths [Tolerance = 0.2mm]; rule Impedance Constraint [Min = 85.00    Max = 95.00    ]: USB_OTGHS_CN_N, USB_OTGHS_CN_P, USB_OTGHS_N, USB_OTGHS_P

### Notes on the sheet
- PH10
- (near R16) PH12
- VBUS OK
- (near U13) Active high
- PB13
- PB14
- PB15
- PB12

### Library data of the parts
C78 = Cap_4.7uF_X5R_10%_0603: Capacitor,4.7uF,16V, X5R,10%,0603,YAGEO; Manuf_Part_1: CC0603KRX5R7BB475; Order: CC0603KRX5R7BB105; Ordered by: Subcon; Fitted: YES
CN19 = 475900001: USB-MICRO-AB, 47590-0001, SMT, MOLEX; Ordered by: Subcon; Fitted: YES
LD7 = LED_red: LED red 0603; Manuf_1: everlight; Manuf_Part_1: 19-213-R6C-AP1Q2B/3T; Ordered by: Subcon; Fitted: YES
LD8 = LED_green: LED green 0603; Manuf_1: everlight; Manuf_Part_1: 19-213SYGC/S530-E2/TR8; Ordered by: Subcon; Fitted: YES
R16 R74 = Res_47K_1%_0402: Resistor,47K,0402,1%,YAGEO; Manuf_Part_1: RC0402FR-0747KL; Order: 9239430; Ordered by: Subcon; Fitted: YES
R75 = Res_100K_1%_0402: Resistor,100K,0402,1%,YAGEO; Manuf_Part_1: RC0402FR-07100KL; Manuf_Part_2: RT0402FRE07100KL; Ordered by: Subcon; Fitted: YES
R78 = Res_0_5%_0402: as R49 on sheet STM32F7
R80 = Res_3K3_1%_0402: Resistor,3K3,0402,1%,YAGEO; Manuf_Part_1: RC0402FR-073K3L; Ordered by: Subcon; Fitted: YES
R81 = Res_620_1%_0603: Resistor,620,0603,1%,VISHAY; Manuf_Part_1: CRCW0603620RFKEA; Manuf_1: VISHAY DRALORIC; Order: 2122341; Ordered by: Subcon; Fitted: YES
R82 = Res_330_1%_0603: Resistor,330,0603,1%,YAGEO; Manuf_Part_1: RC0603FR-07330RL; Manuf_Part_2: RT0603FRE07330RL; Ordered by: Subcon; Fitted: YES
R98 = Res_0_5%_0805: Resistor,0,0805,5%,YAGEO; Manuf_Part_1: RC0805JR-070RL; Value: 0; Order: 2363489; Fitted: YES; Ordered by: Subcon
T1 = 9013-SOT23: NPN Bipolar Transistor; Manuf_1: NXP; Manuf_Part_1: BSR14; Order: 1081310; Ordered by: Subcon; Fitted: YES
U13 = STMPS2151STR: Enhanced single channel power switches; Manuf_1: STM; Provided: ST; ECCN_US/EU: EAR99/NEC; Fitted: YES
U15 = ECMF02-4CMX8: Common mode filter with ESD protection for USB 2.0 interface; Manuf_1: STM; Provided: ST; ECCN_US/EU: EAR99/NEC; Fitted: YES

## Sheet QSPI.SchDoc: Quad SPI Flash Memory (MICRON)
size A4; Author: N.P; CompanyName: STMicroelectronics; Organization: MCD/APPLIS/LMS; DocumentNumber: MB1260; Revision: D-01; SheetNumber: 6; SheetTotal: 12; Project: STM32F723e-DISCO; BOM Version: D-01
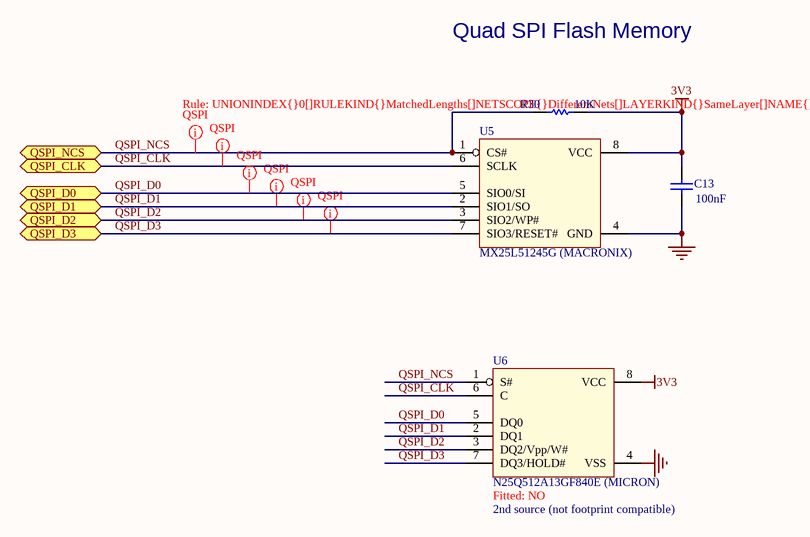
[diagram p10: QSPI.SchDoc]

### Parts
C13  100nF  [0402C]
R30  10K  [0402R]
U5  MX25L51245G (MACRONIX)  [SON8_1R27_6X8]
U6  N25Q512A13GF840E (MICRON)  Fitted: NO  [DFN8_1R27_6X8_TP4R6X5R3]

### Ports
QSPI_CLK, QSPI_D0, QSPI_D1, QSPI_D2, QSPI_D3, QSPI_NCS

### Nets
3V3: C13.2 R30.2 U5.8(VCC) U6.8(VCC)
GND: C13.1 U5.4(GND) U6.4(VSS)
QSPI_CLK: U5.6(SCLK) U6.6(C) ; port QSPI_CLK
QSPI_D0: U5.5(SIO0/SI) U6.5(DQ0) ; port QSPI_D0
QSPI_D1: U5.2(SIO1/SO) U6.2(DQ1) ; port QSPI_D1
QSPI_D2: U5.3(SIO2/WP#) U6.3(DQ2/Vpp/W#) ; port QSPI_D2
QSPI_D3: U5.7(SIO3/RESET#) U6.7(DQ3/HOLD#) ; port QSPI_D3
QSPI_NCS: R30.1 U5.1(CS#) U6.1(S#) ; port QSPI_NCS

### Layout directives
rule Matched Net Lengths [Tolerance = 100mil]: QSPI_CLK, QSPI_D0, QSPI_D1, QSPI_D2, QSPI_D3, QSPI_NCS

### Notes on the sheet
- Quad SPI Flash Memory
- (near U6) 2nd source (not footprint compatible)

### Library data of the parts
C13 = Cap_100nF_X7R_10%_0402: as C36-C40 on sheet STM32F7
R30 = Res_10K_1%_0402: as R36 on sheet STM32F7
U5 = MX25L51245G: 512Mb, 3V, Multiple I/O Serial Flash Memory, Quad/Dual; Manuf_Part_1: MX25L51245GZ2I-08G; Manuf_Part_2: MX25L51245GZ2I-10G; Provided: Subcon; Ref St: xxxxxxxxxx; Fitted: YES
U6 = N25Q512A13GF840E: 512Mb, 3V, Multiple I/O Serial Flash Memory, Quad/Dual; ECCN_US/EU: 3A991/NEC; Provided: ST; Ref St: xxxxxxxx

## Sheet HW_Mechanical_Parts.SchDoc: HW Mechanical parts
size A4; Date: 19/04/2016; Author: N.P; CompanyName: STMicroelectronics; Organization: MCD/APPLIS/LMS; DocumentNumber: MB1260; Revision: D-01; SheetNumber: 12; SheetTotal: 12; Project: STM32F723e-DISCO; BOM Version: D-01
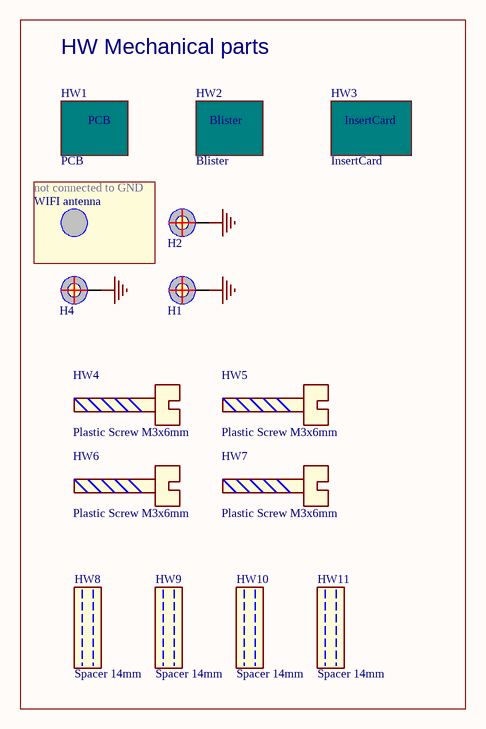
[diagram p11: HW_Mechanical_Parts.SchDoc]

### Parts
H1  POSITION HOLE C6D3R5  [HOLE_C6D3R5]  (value not drawn)  (no BOM)
H2  POSITION HOLE C6D3R5  [HOLE_C6D3R5]  (value not drawn)  (no BOM)
H4  POSITION HOLE C6D3R5  [HOLE_C6D3R5]  (value not drawn)  (no BOM)
HW1  PCB
HW2  Blister
HW3  InsertCard
HW4  Plastic Screw M3x6mm  (mechanical)
HW5  Plastic Screw M3x6mm  (mechanical)
HW6  Plastic Screw M3x6mm  (mechanical)
HW7  Plastic Screw M3x6mm  (mechanical)
HW8  Spacer 14mm  (mechanical)
HW9  Spacer 14mm  (mechanical)
HW10  Spacer 14mm  (mechanical)
HW11  Spacer 14mm  (mechanical)

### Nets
GND: H1.1 H2.1 H4.1

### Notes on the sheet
- HW Mechanical parts
- (near H2) not connected to GND
- WIFI antenna

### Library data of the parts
H1 H2 H4 = POSITION HOLE C6D3R5: Fitted: NO; Ordered by: Subcon
HW1 = PCB: Manuf_Part_1: MB1260 PCB; Manuf_1: Jiubaba; Ordered by: Subcon; Fitted: YES
HW2 = Blister: Manuf_Part_1: MB1260 Blister; Manuf_1: Jiubaba; Ordered by: Subcon; Fitted: YES
HW3 = InsertCard: Manuf_Part_1: MB1260 InsertCard; Manuf_1: Jiubaba; Ordered by: Subcon; Fitted: YES
HW4-HW7 = Plastic Screw M3x6mm: Plastic screw; Ordered_By: Subcon; Fitted: YES
HW8-HW11 = Plastic Spacer D4.5x14, M3x0.5: Plastic spacer; Manuf_1: RAF; Manuf_Part_1: M1261-3005-N; Ordered_By: Subcon; Fitted: YES

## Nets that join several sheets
1V8: ST_LINK_V2-1 (C57.2 U9.2 U9.4), AUDIO (6 pins)
3V3: ST_LINK_V2-1 (C15.2 C16.2 U4.4 U9.3), AUDIO (11 pins), Peripherals (13 pins), ARDUINO (CN12.2 CN12.4), PSRAM (6 pins), USB_OTG_FS (R73.2 R79.2 R83.2 R84.2), STM32F7 (14 pins), LCD_FRIDA (6 pins), USB_OTG_HS (R80.1 R81.1 R82.2), QSPI (C13.2 R30.2 U5.8 U6.8)
5V: ST_LINK_V2-1 (11 pins), Peripherals (P1.6 P1.15), ARDUINO (CN12.5), USB_OTG_FS (U14.5), LCD_FRIDA (L3.1), USB_OTG_HS (U13.5)
5V_USB_FS: ST_LINK_V2-1 (CN8.7 D3.1), USB_OTG_FS (R99.2)
5V_USB_HS: ST_LINK_V2-1 (CN8.3 D5.1), USB_OTG_HS (6 pins)
E5V: ST_LINK_V2-1 (6 pins), ARDUINO (R58.2)
GND: ST_LINK_V2-1 (55 pins), AUDIO (41 pins), Peripherals (15 pins), ARDUINO (5 pins), PSRAM (5 pins), USB_OTG_FS (13 pins), STM32F7 (70 pins), LCD_FRIDA (12 pins), USB_OTG_HS (13 pins), QSPI (C13.1 U5.4 U6.4), HW_Mechanical_Parts (H1.1 H2.1 H4.1)
VDD: STM32F7 (34 pins), LCD_FRIDA (CN17.25 R68.1 R70.1 SB15.1)
VIN: ST_LINK_V2-1 (C74.2 U11.3), ARDUINO (CN12.8)
VREF+: ARDUINO (C50.2 R53.2), STM32F7 (C59.2 C64.1 R62.1 U8.P1)
ARD_A0: ARDUINO (CN15.1), STM32F7 (U8.P3)
ARD_A1: Peripherals (SB28.2), ARDUINO (CN15.2), STM32F7 (U8.N4)
ARD_A2: ARDUINO (CN15.3), STM32F7 (U8.N5)
ARD_A3: ARDUINO (CN15.4), STM32F7 (U8.L1)
ARD_A4: ARDUINO (SB35.1), STM32F7 (U8.M2)
ARD_A5: ARDUINO (SB37.1), STM32F7 (U8.M3)
ARD_D0: ARDUINO (CN13.1), STM32F7 (U8.R2)
ARD_D1: ARDUINO (CN13.2), STM32F7 (U8.P2)
ARD_D2: ARDUINO (CN13.3), STM32F7 (U8.P5)
ARD_D3: ARDUINO (CN13.4), STM32F7 (U8.B2)
ARD_D4: ARDUINO (CN13.5), STM32F7 (U8.G4)
ARD_D5: Peripherals (SB29.2), ARDUINO (CN13.6), STM32F7 (U8.R5)
ARD_D6: ARDUINO (CN13.7), STM32F7 (U8.B3)
ARD_D7: ARDUINO (CN13.8), STM32F7 (U8.A1)
ARD_D8: ARDUINO (CN11.1), STM32F7 (U8.B1)
ARD_D9: ARDUINO (CN11.2), STM32F7 (U8.M11)
ARD_D10: ARDUINO (CN11.3), STM32F7 (U8.N2)
ARD_D11: ARDUINO (CN11.4), STM32F7 (U8.A6)
ARD_D12: ARDUINO (CN11.5), STM32F7 (U8.A9)
ARD_D13: ARDUINO (CN11.6 SB14.2), STM32F7 (U8.P4)
ARD_D14: Peripherals (SB27.1), ARDUINO (CN11.9 SB36.1), STM32F7 (R59.1 U8.J4)
ARD_D15: Peripherals (SB25.1), ARDUINO (CN11.10 SB38.1), STM32F7 (R60.1 U8.H4)
CTP_INT: STM32F7 (U8.D3), LCD_FRIDA (CN16.2 R21.2)
CTP_RST: STM32F7 (U8.M13), LCD_FRIDA (CN16.7 R18.2)
CTP_SCL: STM32F7 (R52.2 U8.F15), LCD_FRIDA (CN16.5)
CTP_SDA: STM32F7 (R56.1 U8.M12), LCD_FRIDA (CN16.4)
LCD-RS_A0: STM32F7 (R101.2), LCD_FRIDA (CN17.21)
LCD_BL: STM32F7 (U8.L12), LCD_FRIDA (L7.1)
LCD_NE: STM32F7 (U8.C10), LCD_FRIDA (CN17.22 R70.2)
LCD_PSRAM_D0: PSRAM (U10.B6), STM32F7 (U8.M14), LCD_FRIDA (CN17.18)
LCD_PSRAM_D1: PSRAM (U10.C5), STM32F7 (U8.L14), LCD_FRIDA (CN17.17)
LCD_PSRAM_D2: PSRAM (U10.C6), STM32F7 (U8.B12), LCD_FRIDA (CN17.16)
LCD_PSRAM_D3: PSRAM (U10.D5), STM32F7 (U8.C12), LCD_FRIDA (CN17.15)
LCD_PSRAM_D4: PSRAM (U10.E5), STM32F7 (U8.R8), LCD_FRIDA (CN17.14)
LCD_PSRAM_D5: PSRAM (U10.F5), STM32F7 (U8.P8), LCD_FRIDA (CN17.13)
LCD_PSRAM_D6: PSRAM (U10.F6), STM32F7 (U8.P9), LCD_FRIDA (CN17.12)
LCD_PSRAM_D7: PSRAM (U10.G6), STM32F7 (U8.R9), LCD_FRIDA (CN17.11)
LCD_PSRAM_D8: PSRAM (U10.B1), STM32F7 (U8.P10), LCD_FRIDA (CN17.10)
LCD_PSRAM_D9: PSRAM (U10.C1), STM32F7 (U8.R10), LCD_FRIDA (CN17.9)
LCD_PSRAM_D10: PSRAM (U10.C2), STM32F7 (U8.N11), LCD_FRIDA (CN17.8)
LCD_PSRAM_D11: PSRAM (U10.D2), STM32F7 (U8.P11), LCD_FRIDA (CN17.7)
LCD_PSRAM_D12: PSRAM (U10.E2), STM32F7 (U8.R11), LCD_FRIDA (CN17.6)
LCD_PSRAM_D13: PSRAM (U10.F2), STM32F7 (U8.P15), LCD_FRIDA (CN17.5)
LCD_PSRAM_D14: PSRAM (U10.F1), STM32F7 (U8.P14), LCD_FRIDA (CN17.4)
LCD_PSRAM_D15: PSRAM (U10.G1), STM32F7 (U8.N15), LCD_FRIDA (CN17.3)
LCD_PSRAM_NOE: PSRAM (U10.A2), STM32F7 (U8.D10), LCD_FRIDA (CN17.19)
LCD_PSRAM_NWE: PSRAM (R64.1), STM32F7 (U8.C11), LCD_FRIDA (CN17.20)
LCD_RST: STM32F7 (U8.N12), LCD_FRIDA (CN17.23 R68.2)
LCD_TE_INT: STM32F7 (U8.G14), LCD_FRIDA (CN17.2)
NRST: ST_LINK_V2-1 (R28.2 SB10.2), Peripherals (SB34.1), ARDUINO (CN12.3), STM32F7 (C93.2 R57.1 U8.J1)
PMOD_GPIO_0: Peripherals (P2.9), STM32F7 (U8.B8)
PMOD_GPIO_1: Peripherals (P2.10), STM32F7 (U8.F4)
PMOD_INT: Peripherals (P1.11 P2.7), STM32F7 (U8.R13)
PMOD_RESET: Peripherals (P1.12 P2.8), STM32F7 (U8.R6)
PMOD_SEL_0: Peripherals (R102.1 U20.3), STM32F7 (U8.D13)
PMOD_SEL_1: Peripherals (R29.2 U20.10), STM32F7 (U8.E3)
PMOD_SPI2_MISO: Peripherals (U20.6), STM32F7 (U8.C14)
PMOD_SPI2_MOSI: Peripherals (U20.1), STM32F7 (U8.C13)
PMOD_SPI2_NSS: Peripherals (U20.9), STM32F7 (U8.E14)
PMOD_SPI2_SCK: Peripherals (U20.14), STM32F7 (U8.D14)
PMOD_UART7_CTS: Peripherals (U20.7), STM32F7 (U8.L2)
PMOD_UART7_RTS: Peripherals (U20.12), STM32F7 (U8.L3)
PMOD_UART7_RXD: Peripherals (U20.4), STM32F7 (U8.K2)
PMOD_UART7_TXD: Peripherals (U20.15), STM32F7 (U8.K1)
PSRAM_A0: PSRAM (U10.A3), STM32F7 (R101.1 U8.E2)
PSRAM_A1: PSRAM (U10.A4), STM32F7 (U8.H3)
PSRAM_A2: PSRAM (U10.A5), STM32F7 (U8.H2)
PSRAM_A3: PSRAM (U10.B3), STM32F7 (U8.J2)
PSRAM_A4: PSRAM (U10.B4), STM32F7 (U8.J3)
PSRAM_A5: PSRAM (U10.C3), STM32F7 (U8.K3)
PSRAM_A6: PSRAM (U10.C4), STM32F7 (U8.P6)
PSRAM_A7: PSRAM (U10.D4), STM32F7 (U8.N6)
PSRAM_A8: PSRAM (U10.H2), STM32F7 (U8.R7)
PSRAM_A9: PSRAM (U10.H3), STM32F7 (U8.P7)
PSRAM_A10: PSRAM (U10.H4), STM32F7 (U8.N7)
PSRAM_A11: PSRAM (U10.H5), STM32F7 (U8.M7)
PSRAM_A12: PSRAM (U10.G3), STM32F7 (U8.L15)
PSRAM_A13: PSRAM (U10.G4), STM32F7 (U8.K15)
PSRAM_A14: PSRAM (U10.F3), STM32F7 (U8.K14)
PSRAM_A15: PSRAM (U10.F4), STM32F7 (U8.K13)
PSRAM_A16: PSRAM (U10.E4), STM32F7 (U8.N14)
PSRAM_A17: PSRAM (U10.D3), STM32F7 (U8.N13)
PSRAM_NBL0: PSRAM (U10.A1), STM32F7 (U8.A4)
PSRAM_NBL1: PSRAM (U10.B2), STM32F7 (U8.A3)
PSRAM_NE1: PSRAM (R65.1), STM32F7 (U8.A11)
QSPI_CLK: STM32F7 (U8.M6), QSPI (U5.6 U6.6)
QSPI_D0: STM32F7 (U8.F14), QSPI (U5.5 U6.5)
QSPI_D1: STM32F7 (U8.B14), QSPI (U5.2 U6.2)
QSPI_D2: STM32F7 (U8.A2), QSPI (U5.3 U6.3)
QSPI_D3: STM32F7 (U8.M15), QSPI (U5.7 U6.7)
QSPI_NCS: STM32F7 (U8.B6), QSPI (R30.1 U5.1 U6.1)
SAI2_FS_A: AUDIO (U7.E3), STM32F7 (TP11.1 U8.C2)
SAI2_I2C1_SCL: AUDIO (R39.1), STM32F7 (R44.2 U8.A5)
SAI2_I2C1_SDA: AUDIO (R35.1), STM32F7 (R42.2 U8.B4)
SAI2_INT: AUDIO (U7.G3), STM32F7 (U8.B7)
SAI2_MCLK_A: AUDIO (U7.D3), STM32F7 (TP6.1 U8.D4)
SAI2_SCK_A: AUDIO (U7.G1), STM32F7 (TP7.1 U8.C4)
SAI2_SD_A: AUDIO (U7.E4), STM32F7 (TP12.1 U8.C3)
SAI2_SD_B: AUDIO (U7.F2), STM32F7 (TP4.1 U8.B10)
STMOD+_SPI2_MISOs: Peripherals (P1.9), STM32F7 (U8.M4)
STMOD+_SPI2_MOSIs: Peripherals (P1.8), STM32F7 (U8.M5)
STMOD+_TIM2_CH1: Peripherals (P1.19), STM32F7 (U8.A13)
STMOD+_UART4_RXD: Peripherals (P1.18), STM32F7 (U8.E13)
STMOD+_UART4_RXD_s: Peripherals (P1.20), STM32F7 (U8.B13)
STMOD+_UART4_TXD: Peripherals (P1.17), STM32F7 (U8.E12)
SYS_B_USER: Peripherals (SB33.1), STM32F7 (U8.N3)
SYS_LD_USER1: Peripherals (R47.1), STM32F7 (U8.R3)
SYS_LD_USER2: Peripherals (R48.1), STM32F7 (U8.R4)
SYS_STLINK_JTCK: ST_LINK_V2-1 (R38.2 SB12.2), STM32F7 (U8.A14)
SYS_STLINK_JTDO-SWO: ST_LINK_V2-1 (R40.2 SB13.2), STM32F7 (U8.A10)
SYS_STLINK_JTMS: ST_LINK_V2-1 (R32.2 SB11.2), STM32F7 (U8.A15)
USB_OTGFS_ID: USB_OTG_FS (CN18.4 U23.1), STM32F7 (U8.D15)
USB_OTGFS_N: USB_OTG_FS (U22.1), STM32F7 (U8.C15)
USB_OTGFS_OVCR: USB_OTG_FS (LD10.2 R79.1 U14.3), STM32F7 (U8.R12)
USB_OTGFS_P: USB_OTG_FS (U22.3), STM32F7 (U8.B15)
USB_OTGFS_PPWR_EN: USB_OTG_FS (R72.1), STM32F7 (U8.H14)
USB_OTGFS_VBUS: USB_OTG_FS (6 pins), STM32F7 (U8.E15)
USB_OTGHS_ID: STM32F7 (U8.P12), USB_OTG_HS (CN19.4 U15.4)
USB_OTGHS_N: STM32F7 (U8.R14), USB_OTG_HS (U15.7)
USB_OTGHS_OVCR: STM32F7 (U8.L13), USB_OTG_HS (R78.2)
USB_OTGHS_P: STM32F7 (U8.R15), USB_OTG_HS (U15.6)
USB_OTGHS_PPWR_EN: STM32F7 (U8.K12), USB_OTG_HS (R16.2 U13.4)
USB_OTGHS_VBUS: STM32F7 (U8.P13), USB_OTG_HS (R98.1)
VCP_RX: ST_LINK_V2-1 (CN6.2 SB8.1), STM32F7 (U8.G15)
VCP_TX: ST_LINK_V2-1 (CN6.1 SB9.1), STM32F7 (U8.H15)
WIFI_CH_PD: Peripherals (CN14.6 R95.2), STM32F7 (U8.D11)
WIFI_GPIO_0: Peripherals (CN14.3 R93.2), STM32F7 (U8.A8)
WIFI_GPIO_2: Peripherals (CN14.5 R96.2), STM32F7 (U8.B11)
WIFI_RST: Peripherals (CN14.4 R94.2), STM32F7 (U8.A7)
WIFI_RX: Peripherals (R92.1), STM32F7 (U8.A12)
WIFI_TX: Peripherals (R97.2), STM32F7 (U8.D12)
